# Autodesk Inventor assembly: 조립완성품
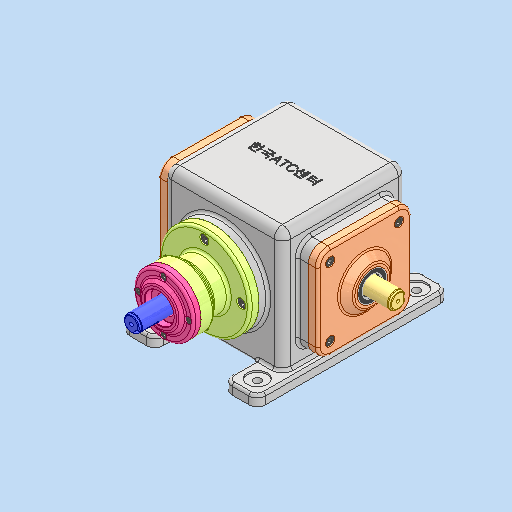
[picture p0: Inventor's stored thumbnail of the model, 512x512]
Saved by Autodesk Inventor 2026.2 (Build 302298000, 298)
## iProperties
Created: 2026-01
Part Number: 조립완성품
Document SubType Name: Assembly
Designer: PC2-07
Author: PC2-07
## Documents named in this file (16)
- C:\Users\PC2-07\Desktop\760103V1005\조립완성품.iam
- C:\Users\PC2-07\Desktop\760103V1005\본체.ipt
- C:\Users\PC2-07\Desktop\760103V1005\종동축\종동축\종동축.ipt
- C:\Users\PC2-07\Desktop\760103V1005\테이퍼 롤러 베어링 30204K\테이퍼 롤러 베어링 30204K\테이퍼 롤러 베어링 30204K.ipt
- C:\Users\PC2-07\Desktop\760103V1005\평행 키 6x6x18\평행 키 6x6x18\평행 키 6x6x18.ipt
- C:\Users\PC2-07\Desktop\760103V1005\베벨 기어(종동)\베벨 기어(종동)\베벨 기어(종동).ipt
- C:\Users\PC2-07\Desktop\760103V1005\칼라\칼라\칼라.ipt
- C:\Users\PC2-07\Desktop\760103V1005\측면 커버\측면 커버\측면 커버.ipt
- C:\Users\PC2-07\Desktop\760103V1005\오일 실 20 35 8\오일 실 20 35 8\오일 실 20 35 8.ipt
- C:\Users\PC2-07\Desktop\760103V1005\베어링 하우징\베어링 하우징\베어링 하우징.ipt
- C:\Users\PC2-07\Desktop\760103V1005\하우징 커버\하우징 커버\하우징 커버.ipt
- C:\Users\PC2-07\Desktop\760103V1005\구동축\구동축\구동축.ipt
- C:\Users\PC2-07\Desktop\760103V1005\베벨 기어(구동)\베벨 기어(구동)\베벨 기어(구동).ipt
- C:\Users\PC2-07\Desktop\760103V1005\엔드캡\엔드캡\엔드캡.ipt
- C:\Users\PC2-07\Desktop\760103V1005\6각 구멍붙이 볼트 M6x12\6각 구멍붙이 볼트 M6x12\6각 구멍붙이 볼트 M6x12.ipt
- C:\Users\PC2-07\Desktop\760103V1005\6각 구멍붙이 볼트 M4x10\6각 구멍붙이 볼트 M4x10\6각 구멍붙이 볼트 M4x10.ipt
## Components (19 placed, 4 different names)
1. 하우징 커버:1
2. 구동축:1
3. 6각 구멍붙이 볼트 M6x12:1
4. 6각 구멍붙이 볼트 M6x12:2
5. 6각 구멍붙이 볼트 M6x12:3
6. 6각 구멍붙이 볼트 M6x12:4
7. 6각 구멍붙이 볼트 M6x12:5
8. 6각 구멍붙이 볼트 M6x12:6
9. 6각 구멍붙이 볼트 M6x12:7
10. 6각 구멍붙이 볼트 M6x12:8
11. 6각 구멍붙이 볼트 M6x12:9
12. 6각 구멍붙이 볼트 M6x12:10
13. 6각 구멍붙이 볼트 M6x12:11
14. 6각 구멍붙이 볼트 M6x12:12
15. 6각 구멍붙이 볼트 M6x12:13
16. 6각 구멍붙이 볼트 M4x10:1
17. 6각 구멍붙이 볼트 M4x10:2
18. 6각 구멍붙이 볼트 M4x10:3
19. 6각 구멍붙이 볼트 M4x10:4
